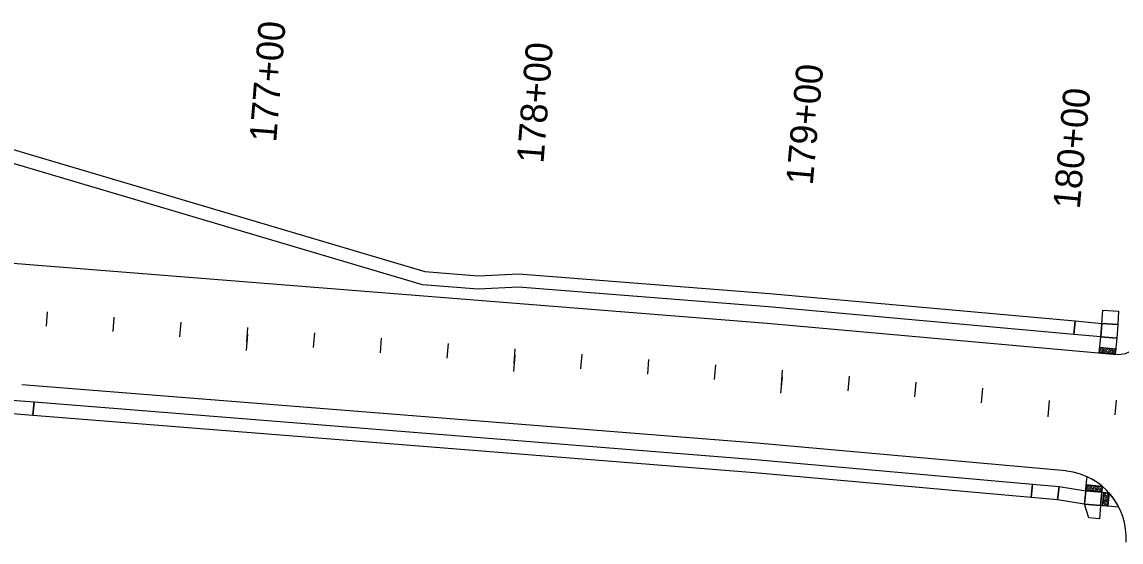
# Model space of a CAD drawing. Extents: x 20499216 to 20505321, y 7953487 to 7960535.
# Drawn here: x 20501326 to 20501735.9, y 7953850 to 7954043.9 of the extents above; entities that cross this region are included whole.
import ezdxf

# ---------------------------------------------------------------- set-up
doc = ezdxf.new("R2010")
doc.units = 0
for name, color, linetype in [('Drainage', 7, 'Continuous'), ('EXT_CU', 7, 'Continuous'), ('EXT_RR', 7, 'Continuous'), ('NamedBoundary', 7, 'Continuous'), ('Roadways', 7, 'Continuous'), ('Safety', 7, 'Continuous')]:
    doc.layers.add(name, color=color, linetype=linetype)

msp = doc.modelspace()

# ---------------------------------------------------------------- linework, layer by layer
at = {"layer": 'Drainage'}
for points in [[(20501729.07, 7953936.47), (20501734.99, 7953936.05), (20501734.63, 7953931.06), (20501728.74, 7953931.48)], [(20501718.78, 7953932.38), (20501728.75, 7953931.48), (20501728.29, 7953926.5), (20501718.33, 7953927.4)], [(20501728.29, 7953926.5), (20501734.26, 7953925.92), (20501733.69, 7953920), (20501727.71, 7953920.53)], [(20501330.05, 7953897.2), (20501315.1, 7953898.39), (20501315.5, 7953903.38), (20501330.45, 7953902.19)], [(20501712.8, 7953870.66), (20501712.18, 7953865.7), (20501702.4, 7953866.57), (20501702.84, 7953871.55)], [(20501722.08, 7953864.1), (20501712.18, 7953865.7), (20501712.8, 7953870.66), (20501722.7, 7953869.06), (20501722.25, 7953864.08)], [(20501722.91, 7953871.24), (20501728.89, 7953870.71), (20501728.69, 7953868.53), (20501722.7, 7953869.06)], [(20501730.94, 7953863.3), (20501728.23, 7953863.55), (20501728.68, 7953868.53), (20501731.39, 7953868.28)], [(20501727.8, 7953858.68), (20501723.86, 7953859.03), (20501722.25, 7953864.08), (20501728.23, 7953863.55), (20501727.8, 7953858.68)]]:
    msp.add_lwpolyline(points, close=True, dxfattribs=at)
for points in [[(20501728.89, 7953870.71), (20501722.91, 7953871.24), (20501723.21, 7953874.31)], [(20501735.06, 7953862.94), (20501730.94, 7953863.3), (20501731.39, 7953868.28)]]:
    msp.add_lwpolyline(points, dxfattribs=at)
for start, end in [(49.8891, 65.3451), (26.9932, 41.8993)]:
    msp.add_arc((20501712.78, 7953851.59), 25, start, end, dxfattribs=at)
at = {"layer": 'EXT_CU'}
for p, q in [((20501727.71, 7953920.58), (20501727.91, 7953922.57)), ((20501733.69, 7953920), (20501727.71, 7953920.58)), ((20501727.91, 7953922.57), (20501733.88, 7953921.99)), ((20501733.88, 7953921.99), (20501733.69, 7953920)), ((20501722.73, 7953869.25), (20501722.91, 7953871.24)), ((20501728.71, 7953868.72), (20501722.73, 7953869.25)), ((20501722.91, 7953871.24), (20501728.89, 7953870.71)), ((20501728.89, 7953870.71), (20501728.71, 7953868.72)), ((20501728.95, 7953863.48), (20501729.4, 7953868.46)), ((20501729.4, 7953868.46), (20501731.39, 7953868.28)), ((20501731.39, 7953868.28), (20501730.94, 7953863.3)), ((20501730.94, 7953863.3), (20501728.95, 7953863.48))]:
    msp.add_line(p, q, dxfattribs=at)
for points in [[(20500965.3, 7953991.78), (20501114.4, 7954012.75), (20501316.65, 7953998.09), (20501476.2, 7953950.79), (20501496.14, 7953949.21), (20501511.25, 7953950.02), (20501604.78, 7953942.58), (20501718.78, 7953932.38), (20501718.33, 7953927.4), (20501604.36, 7953937.6), (20501511.18, 7953945), (20501496.07, 7953944.2), (20501475.28, 7953945.85), (20501320.22, 7953991.82), (20501114.61, 7954006.72), (20500966.14, 7953985.84), (20500961.2, 7953986.29), (20500961.66, 7953991.27)], [(20501702.4, 7953866.57), (20501599.14, 7953875.82), (20501330.05, 7953897.2), (20501330.45, 7953902.19), (20501599.56, 7953880.8), (20501702.84, 7953871.55)]]:
    msp.add_lwpolyline(points, close=True, dxfattribs=at)
for centre, radius in [((20501729.54, 7953867.52), 0.0375), ((20501729.54, 7953867.52), 0.0187), ((20501729.57, 7953867.91), 0.0375), ((20501729.57, 7953867.91), 0.0187), ((20501729.61, 7953868.3), 0.0375), ((20501729.61, 7953868.3), 0.0187), ((20501729.93, 7953867.49), 0.0375), ((20501729.93, 7953867.49), 0.0187), ((20501729.96, 7953867.88), 0.0375), ((20501729.96, 7953867.88), 0.0187), ((20501730, 7953868.27), 0.0375), ((20501730, 7953868.27), 0.0187), ((20501730.32, 7953867.45), 0.0375), ((20501730.32, 7953867.45), 0.0187), ((20501730.35, 7953867.84), 0.0375), ((20501730.35, 7953867.84), 0.0187), ((20501730.39, 7953868.23), 0.0375), ((20501730.39, 7953868.23), 0.0187), ((20501730.71, 7953867.42), 0.0375), ((20501730.71, 7953867.42), 0.0187), ((20501730.74, 7953867.81), 0.0375), ((20501730.74, 7953867.81), 0.0187), ((20501730.78, 7953868.2), 0.0375), ((20501730.78, 7953868.2), 0.0187), ((20501731.1, 7953867.38), 0.0375), ((20501731.1, 7953867.38), 0.0187), ((20501731.13, 7953867.77), 0.0375), ((20501731.13, 7953867.77), 0.0187), ((20501731.17, 7953868.16), 0.0375), ((20501731.17, 7953868.16), 0.0187), ((20501729.19, 7953863.6), 0.0375), ((20501729.19, 7953863.6), 0.0187), ((20501729.22, 7953863.99), 0.0375), ((20501729.22, 7953863.99), 0.0187), ((20501729.26, 7953864.38), 0.0375), ((20501729.26, 7953864.38), 0.0187), ((20501729.29, 7953864.79), 0.0375), ((20501729.29, 7953864.79), 0.0187), ((20501729.33, 7953865.18), 0.0375), ((20501729.33, 7953865.18), 0.0187), ((20501729.36, 7953865.57), 0.0375), ((20501729.36, 7953865.57), 0.0187), ((20501729.4, 7953865.96), 0.0375), ((20501729.4, 7953865.96), 0.0187), ((20501729.43, 7953866.35), 0.0375), ((20501729.43, 7953866.35), 0.0187), ((20501729.47, 7953866.74), 0.0375), ((20501729.47, 7953866.74), 0.0187), ((20501729.5, 7953867.13), 0.0375), ((20501729.5, 7953867.13), 0.0187), ((20501729.58, 7953863.57), 0.0375), ((20501729.58, 7953863.57), 0.0187), ((20501729.61, 7953863.96), 0.0375), ((20501729.61, 7953863.96), 0.0187), ((20501729.65, 7953864.35), 0.0375), ((20501729.65, 7953864.35), 0.0187), ((20501729.68, 7953864.76), 0.0375), ((20501729.68, 7953864.76), 0.0187), ((20501729.72, 7953865.15), 0.0375), ((20501729.72, 7953865.15), 0.0187), ((20501729.75, 7953865.54), 0.0375), ((20501729.75, 7953865.54), 0.0187), ((20501729.79, 7953865.93), 0.0375), ((20501729.79, 7953865.93), 0.0187), ((20501729.82, 7953866.32), 0.0375), ((20501729.82, 7953866.32), 0.0187), ((20501729.86, 7953866.71), 0.0375), ((20501729.86, 7953866.71), 0.0187), ((20501729.89, 7953867.1), 0.0375), ((20501729.89, 7953867.1), 0.0187), ((20501729.97, 7953863.53), 0.0375), ((20501729.97, 7953863.53), 0.0187), ((20501730, 7953863.92), 0.0375), ((20501730, 7953863.92), 0.0187), ((20501730.04, 7953864.31), 0.0375), ((20501730.04, 7953864.31), 0.0187), ((20501730.07, 7953864.72), 0.0375), ((20501730.07, 7953864.72), 0.0187), ((20501730.11, 7953865.11), 0.0375), ((20501730.11, 7953865.11), 0.0187), ((20501730.14, 7953865.5), 0.0375), ((20501730.14, 7953865.5), 0.0187), ((20501730.18, 7953865.89), 0.0375), ((20501730.18, 7953865.89), 0.0187), ((20501730.21, 7953866.28), 0.0375), ((20501730.21, 7953866.28), 0.0187), ((20501730.25, 7953866.67), 0.0375), ((20501730.25, 7953866.67), 0.0187), ((20501730.28, 7953867.06), 0.0375), ((20501730.28, 7953867.06), 0.0187), ((20501730.36, 7953863.5), 0.0375), ((20501730.36, 7953863.5), 0.0187), ((20501730.39, 7953863.89), 0.0375), ((20501730.39, 7953863.89), 0.0187), ((20501730.43, 7953864.28), 0.0375), ((20501730.43, 7953864.28), 0.0187), ((20501730.46, 7953864.69), 0.0375), ((20501730.46, 7953864.69), 0.0187), ((20501730.5, 7953865.08), 0.0375), ((20501730.5, 7953865.08), 0.0187), ((20501730.53, 7953865.47), 0.0375), ((20501730.53, 7953865.47), 0.0187), ((20501730.57, 7953865.86), 0.0375), ((20501730.57, 7953865.86), 0.0187), ((20501730.6, 7953866.25), 0.0375), ((20501730.6, 7953866.25), 0.0187), ((20501730.64, 7953866.64), 0.0375), ((20501730.64, 7953866.64), 0.0187), ((20501730.67, 7953867.03), 0.0375), ((20501730.67, 7953867.03), 0.0187), ((20501730.75, 7953863.46), 0.0375), ((20501730.75, 7953863.46), 0.0187), ((20501730.78, 7953863.85), 0.0375), ((20501730.78, 7953863.85), 0.0187), ((20501730.82, 7953864.24), 0.0375), ((20501730.82, 7953864.24), 0.0187), ((20501730.85, 7953864.65), 0.0375), ((20501730.85, 7953864.65), 0.0187), ((20501730.89, 7953865.04), 0.0375), ((20501730.89, 7953865.04), 0.0187), ((20501730.92, 7953865.43), 0.0375), ((20501730.92, 7953865.43), 0.0187), ((20501730.96, 7953865.82), 0.0375), ((20501730.96, 7953865.82), 0.0187), ((20501730.99, 7953866.21), 0.0375), ((20501730.99, 7953866.21), 0.0187), ((20501731.03, 7953866.6), 0.0375), ((20501731.03, 7953866.6), 0.0187), ((20501731.06, 7953866.99), 0.0375), ((20501731.06, 7953866.99), 0.0187)]:
    msp.add_circle(centre, radius, dxfattribs=at)
for centre, major_axis in [((20501727.9, 7953920.77), (-0.0448, 0.0044)), ((20501727.9, 7953920.77), (-0.0224, 0.0022)), ((20501727.94, 7953921.16), (-0.0448, 0.0044)), ((20501727.94, 7953921.16), (-0.0224, 0.0022)), ((20501727.98, 7953921.55), (-0.0448, 0.0044)), ((20501727.98, 7953921.55), (-0.0224, 0.0022)), ((20501728.01, 7953921.94), (-0.0448, 0.0044)), ((20501728.01, 7953921.94), (-0.0224, 0.0022)), ((20501728.05, 7953922.33), (-0.0448, 0.0044)), ((20501728.05, 7953922.33), (-0.0224, 0.0022)), ((20501728.37, 7953920.73), (-0.0448, 0.0044)), ((20501728.37, 7953920.73), (-0.0224, 0.0022)), ((20501728.4, 7953921.12), (-0.0448, 0.0044)), ((20501728.4, 7953921.12), (-0.0224, 0.0022)), ((20501728.44, 7953921.51), (-0.0448, 0.0044)), ((20501728.44, 7953921.51), (-0.0224, 0.0022)), ((20501728.48, 7953921.9), (-0.0448, 0.0044)), ((20501728.48, 7953921.9), (-0.0224, 0.0022)), ((20501728.52, 7953922.29), (-0.0448, 0.0044)), ((20501728.52, 7953922.29), (-0.0224, 0.0022)), ((20501728.83, 7953920.68), (-0.0448, 0.0044)), ((20501728.83, 7953920.68), (-0.0224, 0.0022)), ((20501728.87, 7953921.07), (-0.0448, 0.0044)), ((20501728.87, 7953921.07), (-0.0224, 0.0022)), ((20501728.91, 7953921.46), (-0.0448, 0.0044)), ((20501728.91, 7953921.46), (-0.0224, 0.0022)), ((20501728.95, 7953921.85), (-0.0448, 0.0044)), ((20501728.95, 7953921.85), (-0.0224, 0.0022)), ((20501728.99, 7953922.24), (-0.0448, 0.0044)), ((20501728.99, 7953922.24), (-0.0224, 0.0022)), ((20501729.33, 7953920.63), (-0.0448, 0.0044)), ((20501729.33, 7953920.63), (-0.0224, 0.0022)), ((20501729.37, 7953921.02), (-0.0448, 0.0044)), ((20501729.37, 7953921.02), (-0.0224, 0.0022)), ((20501729.4, 7953921.41), (-0.0448, 0.0044)), ((20501729.4, 7953921.41), (-0.0224, 0.0022)), ((20501729.44, 7953921.8), (-0.0448, 0.0044)), ((20501729.44, 7953921.8), (-0.0224, 0.0022)), ((20501729.48, 7953922.19), (-0.0448, 0.0044)), ((20501729.48, 7953922.19), (-0.0224, 0.0022)), ((20501729.8, 7953920.59), (-0.0448, 0.0044)), ((20501729.8, 7953920.59), (-0.0224, 0.0022)), ((20501729.83, 7953920.98), (-0.0448, 0.0044)), ((20501729.83, 7953920.98), (-0.0224, 0.0022)), ((20501729.87, 7953921.37), (-0.0448, 0.0044)), ((20501729.87, 7953921.37), (-0.0224, 0.0022)), ((20501729.91, 7953921.76), (-0.0448, 0.0044)), ((20501729.91, 7953921.76), (-0.0224, 0.0022)), ((20501729.95, 7953922.15), (-0.0448, 0.0044)), ((20501729.95, 7953922.15), (-0.0224, 0.0022)), ((20501730.26, 7953920.54), (-0.0448, 0.0044)), ((20501730.3, 7953920.93), (-0.0448, 0.0044)), ((20501730.3, 7953920.93), (-0.0224, 0.0022)), ((20501730.34, 7953921.32), (-0.0448, 0.0044)), ((20501730.34, 7953921.32), (-0.0224, 0.0022)), ((20501730.38, 7953921.71), (-0.0448, 0.0044)), ((20501730.38, 7953921.71), (-0.0224, 0.0022)), ((20501730.41, 7953922.1), (-0.0448, 0.0044)), ((20501730.41, 7953922.1), (-0.0224, 0.0022)), ((20501730.77, 7953920.89), (-0.0448, 0.0044)), ((20501730.77, 7953920.89), (-0.0224, 0.0022)), ((20501730.81, 7953921.28), (-0.0448, 0.0044)), ((20501730.81, 7953921.28), (-0.0224, 0.0022)), ((20501730.84, 7953921.67), (-0.0448, 0.0044)), ((20501730.84, 7953921.67), (-0.0224, 0.0022)), ((20501730.88, 7953922.06), (-0.0448, 0.0044)), ((20501730.88, 7953922.06), (-0.0224, 0.0022)), ((20501731.24, 7953920.84), (-0.0448, 0.0044)), ((20501731.24, 7953920.84), (-0.0224, 0.0022)), ((20501731.27, 7953921.23), (-0.0448, 0.0044)), ((20501731.27, 7953921.23), (-0.0224, 0.0022)), ((20501731.31, 7953921.62), (-0.0448, 0.0044)), ((20501731.31, 7953921.62), (-0.0224, 0.0022)), ((20501731.35, 7953922.01), (-0.0448, 0.0044)), ((20501731.35, 7953922.01), (-0.0224, 0.0022)), ((20501731.7, 7953920.8), (-0.0448, 0.0044)), ((20501731.7, 7953920.8), (-0.0224, 0.0022)), ((20501731.74, 7953921.18), (-0.0448, 0.0044)), ((20501731.74, 7953921.18), (-0.0224, 0.0022)), ((20501731.78, 7953921.57), (-0.0448, 0.0044)), ((20501731.78, 7953921.57), (-0.0224, 0.0022)), ((20501731.82, 7953921.96), (-0.0448, 0.0044)), ((20501731.82, 7953921.96), (-0.0224, 0.0022)), ((20501732.17, 7953920.75), (-0.0448, 0.0044)), ((20501732.17, 7953920.75), (-0.0224, 0.0022)), ((20501732.21, 7953921.14), (-0.0448, 0.0044)), ((20501732.21, 7953921.14), (-0.0224, 0.0022)), ((20501732.25, 7953921.53), (-0.0448, 0.0044)), ((20501732.25, 7953921.53), (-0.0224, 0.0022)), ((20501732.29, 7953921.92), (-0.0448, 0.0044)), ((20501732.29, 7953921.92), (-0.0224, 0.0022)), ((20501732.64, 7953920.7), (-0.0448, 0.0044)), ((20501732.64, 7953920.7), (-0.0224, 0.0022)), ((20501732.68, 7953921.09), (-0.0448, 0.0044)), ((20501732.68, 7953921.09), (-0.0224, 0.0022)), ((20501732.72, 7953921.48), (-0.0448, 0.0044)), ((20501732.72, 7953921.48), (-0.0224, 0.0022)), ((20501732.75, 7953921.87), (-0.0448, 0.0044)), ((20501732.75, 7953921.87), (-0.0224, 0.0022)), ((20501733.11, 7953920.66), (-0.0448, 0.0044)), ((20501733.11, 7953920.66), (-0.0224, 0.0022)), ((20501733.15, 7953921.05), (-0.0448, 0.0044)), ((20501733.15, 7953921.05), (-0.0224, 0.0022)), ((20501733.18, 7953921.44), (-0.0448, 0.0044)), ((20501733.18, 7953921.44), (-0.0224, 0.0022)), ((20501733.22, 7953921.83), (-0.0448, 0.0044)), ((20501733.22, 7953921.83), (-0.0224, 0.0022)), ((20501733.57, 7953920.61), (-0.0448, 0.0044)), ((20501733.57, 7953920.61), (-0.0224, 0.0022)), ((20501733.61, 7953921), (-0.0448, 0.0044)), ((20501733.61, 7953921), (-0.0224, 0.0022)), ((20501733.65, 7953921.39), (-0.0448, 0.0044)), ((20501733.65, 7953921.39), (-0.0224, 0.0022)), ((20501733.69, 7953921.78), (-0.0448, 0.0044)), ((20501733.69, 7953921.78), (-0.0224, 0.0022)), ((20501730.26, 7953920.54), (-0.0224, 0.0022)), ((20501730.73, 7953920.5), (-0.0448, 0.0044)), ((20501730.73, 7953920.5), (-0.0224, 0.0022)), ((20501731.2, 7953920.45), (-0.0448, 0.0044)), ((20501731.2, 7953920.45), (-0.0224, 0.0022)), ((20501731.67, 7953920.41), (-0.0448, 0.0044)), ((20501731.67, 7953920.41), (-0.0224, 0.0022)), ((20501732.13, 7953920.36), (-0.0448, 0.0044)), ((20501732.13, 7953920.36), (-0.0224, 0.0022)), ((20501732.6, 7953920.31), (-0.0448, 0.0044)), ((20501732.6, 7953920.31), (-0.0224, 0.0022)), ((20501733.07, 7953920.27), (-0.0448, 0.0044)), ((20501733.07, 7953920.27), (-0.0224, 0.0022)), ((20501733.54, 7953920.22), (-0.0448, 0.0044)), ((20501733.54, 7953920.22), (-0.0224, 0.0022)), ((20501722.92, 7953869.45), (-0.0448, 0.004)), ((20501722.92, 7953869.45), (-0.0224, 0.002)), ((20501722.95, 7953869.84), (-0.0448, 0.004)), ((20501722.95, 7953869.84), (-0.0224, 0.002)), ((20501722.99, 7953870.23), (-0.0448, 0.004)), ((20501722.99, 7953870.23), (-0.0224, 0.002)), ((20501723.02, 7953870.62), (-0.0448, 0.004)), ((20501723.02, 7953870.62), (-0.0224, 0.002)), ((20501723.06, 7953871.01), (-0.0448, 0.004)), ((20501723.06, 7953871.01), (-0.0224, 0.002)), ((20501723.39, 7953869.4), (-0.0448, 0.004)), ((20501723.39, 7953869.4), (-0.0224, 0.002)), ((20501723.42, 7953869.79), (-0.0448, 0.004)), ((20501723.42, 7953869.79), (-0.0224, 0.002)), ((20501723.46, 7953870.19), (-0.0448, 0.004)), ((20501723.46, 7953870.19), (-0.0224, 0.002)), ((20501723.49, 7953870.58), (-0.0448, 0.004)), ((20501723.49, 7953870.58), (-0.0224, 0.002)), ((20501723.53, 7953870.97), (-0.0448, 0.004)), ((20501723.53, 7953870.97), (-0.0224, 0.002)), ((20501723.86, 7953869.36), (-0.0448, 0.004)), ((20501723.86, 7953869.36), (-0.0224, 0.002)), ((20501723.89, 7953869.75), (-0.0448, 0.004)), ((20501723.89, 7953869.75), (-0.0224, 0.002)), ((20501723.92, 7953870.14), (-0.0448, 0.004)), ((20501723.92, 7953870.14), (-0.0224, 0.002)), ((20501723.96, 7953870.53), (-0.0448, 0.004)), ((20501723.96, 7953870.53), (-0.0224, 0.002)), ((20501723.99, 7953870.92), (-0.0448, 0.004)), ((20501723.99, 7953870.92), (-0.0224, 0.002)), ((20501724.35, 7953869.32), (-0.0448, 0.004)), ((20501724.35, 7953869.32), (-0.0224, 0.002)), ((20501724.38, 7953869.71), (-0.0448, 0.004)), ((20501724.38, 7953869.71), (-0.0224, 0.002)), ((20501724.42, 7953870.1), (-0.0448, 0.004)), ((20501724.42, 7953870.1), (-0.0224, 0.002)), ((20501724.45, 7953870.49), (-0.0448, 0.004)), ((20501724.45, 7953870.49), (-0.0224, 0.002)), ((20501724.49, 7953870.88), (-0.0448, 0.004)), ((20501724.49, 7953870.88), (-0.0224, 0.002)), ((20501724.82, 7953869.28), (-0.0448, 0.004)), ((20501724.82, 7953869.28), (-0.0224, 0.002)), ((20501724.85, 7953869.67), (-0.0448, 0.004)), ((20501724.85, 7953869.67), (-0.0224, 0.002)), ((20501724.89, 7953870.06), (-0.0448, 0.004)), ((20501724.89, 7953870.06), (-0.0224, 0.002)), ((20501724.92, 7953870.45), (-0.0448, 0.004)), ((20501724.92, 7953870.45), (-0.0224, 0.002)), ((20501724.96, 7953870.84), (-0.0448, 0.004)), ((20501724.96, 7953870.84), (-0.0224, 0.002)), ((20501725.28, 7953869.23), (-0.0448, 0.004)), ((20501725.28, 7953869.23), (-0.0224, 0.002)), ((20501725.32, 7953869.63), (-0.0448, 0.004)), ((20501725.32, 7953869.63), (-0.0224, 0.002)), ((20501725.35, 7953870.02), (-0.0448, 0.004)), ((20501725.35, 7953870.02), (-0.0224, 0.002)), ((20501725.39, 7953870.41), (-0.0448, 0.004)), ((20501725.39, 7953870.41), (-0.0224, 0.002)), ((20501725.42, 7953870.8), (-0.0448, 0.004)), ((20501725.42, 7953870.8), (-0.0224, 0.002)), ((20501725.75, 7953869.19), (-0.0448, 0.004)), ((20501725.75, 7953869.19), (-0.0224, 0.002)), ((20501725.79, 7953869.58), (-0.0448, 0.004)), ((20501725.79, 7953869.58), (-0.0224, 0.002)), ((20501725.82, 7953869.97), (-0.0448, 0.004)), ((20501725.82, 7953869.97), (-0.0224, 0.002)), ((20501725.86, 7953870.36), (-0.0448, 0.004)), ((20501725.86, 7953870.36), (-0.0224, 0.002)), ((20501725.89, 7953870.75), (-0.0448, 0.004)), ((20501725.89, 7953870.75), (-0.0224, 0.002)), ((20501726.22, 7953869.15), (-0.0448, 0.004)), ((20501726.22, 7953869.15), (-0.0224, 0.002)), ((20501726.26, 7953869.54), (-0.0448, 0.004)), ((20501726.26, 7953869.54), (-0.0224, 0.002)), ((20501726.29, 7953869.93), (-0.0448, 0.004)), ((20501726.29, 7953869.93), (-0.0224, 0.002)), ((20501726.33, 7953870.32), (-0.0448, 0.004)), ((20501726.33, 7953870.32), (-0.0224, 0.002)), ((20501726.36, 7953870.71), (-0.0448, 0.004)), ((20501726.36, 7953870.71), (-0.0224, 0.002)), ((20501726.69, 7953869.11), (-0.0448, 0.004)), ((20501726.69, 7953869.11), (-0.0224, 0.002)), ((20501726.72, 7953869.5), (-0.0448, 0.004)), ((20501726.72, 7953869.5), (-0.0224, 0.002)), ((20501726.76, 7953869.89), (-0.0448, 0.004)), ((20501726.76, 7953869.89), (-0.0224, 0.002)), ((20501726.79, 7953870.28), (-0.0448, 0.004)), ((20501726.79, 7953870.28), (-0.0224, 0.002)), ((20501726.83, 7953870.67), (-0.0448, 0.004)), ((20501726.83, 7953870.67), (-0.0224, 0.002)), ((20501727.16, 7953869.07), (-0.0448, 0.004)), ((20501727.16, 7953869.07), (-0.0224, 0.002)), ((20501727.19, 7953869.46), (-0.0448, 0.004)), ((20501727.19, 7953869.46), (-0.0224, 0.002)), ((20501727.23, 7953869.85), (-0.0448, 0.004)), ((20501727.23, 7953869.85), (-0.0224, 0.002)), ((20501727.26, 7953870.24), (-0.0448, 0.004)), ((20501727.26, 7953870.24), (-0.0224, 0.002)), ((20501727.3, 7953870.63), (-0.0448, 0.004)), ((20501727.3, 7953870.63), (-0.0224, 0.002)), ((20501727.62, 7953869.03), (-0.0448, 0.004)), ((20501727.62, 7953869.03), (-0.0224, 0.002)), ((20501727.66, 7953869.42), (-0.0448, 0.004)), ((20501727.66, 7953869.42), (-0.0224, 0.002)), ((20501727.69, 7953869.81), (-0.0448, 0.004)), ((20501727.69, 7953869.81), (-0.0224, 0.002)), ((20501727.73, 7953870.2), (-0.0448, 0.004)), ((20501727.73, 7953870.2), (-0.0224, 0.002)), ((20501727.76, 7953870.59), (-0.0448, 0.004)), ((20501727.76, 7953870.59), (-0.0224, 0.002)), ((20501728.09, 7953868.98), (-0.0448, 0.004)), ((20501728.09, 7953868.98), (-0.0224, 0.002)), ((20501728.13, 7953869.37), (-0.0448, 0.004)), ((20501728.13, 7953869.37), (-0.0224, 0.002)), ((20501728.16, 7953869.76), (-0.0448, 0.004)), ((20501728.16, 7953869.76), (-0.0224, 0.002)), ((20501728.2, 7953870.15), (-0.0448, 0.004)), ((20501728.2, 7953870.15), (-0.0224, 0.002)), ((20501728.23, 7953870.54), (-0.0448, 0.004)), ((20501728.23, 7953870.54), (-0.0224, 0.002)), ((20501728.56, 7953868.94), (-0.0448, 0.004)), ((20501728.56, 7953868.94), (-0.0224, 0.002)), ((20501728.6, 7953869.33), (-0.0448, 0.004)), ((20501728.6, 7953869.33), (-0.0224, 0.002)), ((20501728.63, 7953869.72), (-0.0448, 0.004)), ((20501728.63, 7953869.72), (-0.0224, 0.002)), ((20501728.67, 7953870.11), (-0.0448, 0.004)), ((20501728.67, 7953870.11), (-0.0224, 0.002)), ((20501728.7, 7953870.5), (-0.0448, 0.004)), ((20501728.7, 7953870.5), (-0.0224, 0.002))]:
    msp.add_ellipse(centre, major_axis=major_axis, ratio=0.833333, dxfattribs=at)
at = {"layer": 'EXT_RR'}
for p, q in [((20501335.05, 7953930.41), (20501335.48, 7953935.85)), ((20501359.97, 7953928.43), (20501360.4, 7953933.87)), ((20501384.89, 7953926.45), (20501385.33, 7953931.89)), ((20501410.06, 7953927.52), (20501409.57, 7953921.42)), ((20501434.74, 7953922.49), (20501435.17, 7953927.93)), ((20501459.66, 7953920.51), (20501460.09, 7953925.95)), ((20501484.58, 7953918.53), (20501485.01, 7953923.97)), ((20501509.74, 7953919.6), (20501509.26, 7953913.5)), ((20501534.42, 7953914.57), (20501534.85, 7953920.01)), ((20501559.34, 7953912.59), (20501559.78, 7953918.03)), ((20501584.26, 7953910.61), (20501584.7, 7953916.05)), ((20501609.45, 7953911.6), (20501608.91, 7953905.51)), ((20501634.08, 7953906.33), (20501634.57, 7953911.76)), ((20501658.98, 7953904.1), (20501659.47, 7953909.53)), ((20501683.88, 7953901.87), (20501684.37, 7953907.3)), ((20501709.05, 7953902.68), (20501708.51, 7953896.59)), ((20501733.68, 7953897.41), (20501734.17, 7953902.84))]:
    msp.add_line(p, q, dxfattribs=at)
at = {"layer": 'NamedBoundary'}
for points in [[(20500911.34, 7953941.51), (20500848.24, 7953946.53), (20500808.56, 7953950.16), (20500808.63, 7953950.91), (20500808.63, 7953950.91), (20500809.17, 7953955.67), (20500809.06, 7953955.68), (20500812.15, 7953989.44), (20500804.8, 7953990.07), (20500805.25, 7953995.63), (20500812.66, 7953994.97), (20500852.08, 7953991.36), (20501603.86, 7953931.62), (20501734.26, 7953919.95)], [(20501715.63, 7953876.43), (20501715.33, 7953876.46), (20501600.07, 7953886.78), (20501325.96, 7953908.56), (20501325.96, 7953908.56)]]:
    msp.add_lwpolyline(points, dxfattribs=at)
for centre, radius, start, end in [((20501735.01, 7953928.41), 8.5, 264.8834, 354.618), ((20501712.76, 7953851.57), 25.03, 356.3606, 83.4061)]:
    msp.add_arc(centre, radius, start, end, dxfattribs=at)
at = {"layer": 'Roadways'}
for points in [[(20501728.74, 7953931.48), (20501734.63, 7953931.06), (20501734.63, 7953930.96), (20501734.26, 7953925.92), (20501728.29, 7953926.5)], [(20501722.25, 7953864.08), (20501722.7, 7953869.06), (20501728.68, 7953868.53), (20501728.23, 7953863.55)]]:
    msp.add_lwpolyline(points, close=True, dxfattribs=at)
at = {"layer": 'Safety'}
for p, q in [((20501409.81, 7953924.47), (20501410.25, 7953929.91)), ((20501509.5, 7953916.55), (20501509.93, 7953921.99)), ((20501609.18, 7953908.55), (20501609.67, 7953913.99)), ((20501709.05, 7953902.68), (20501708.51, 7953896.59))]:
    msp.add_line(p, q, dxfattribs=at)

# ---------------------------------------------------------------- texts
at = {"layer": 'EXT_RR'}
for s, rotation, p in [('177+00', 85.4564, (20501420.75, 7953998.84)), ('178+00', 85.4564, (20501520.44, 7953990.92)), ('179+00', 84.8834, (20501620.86, 7953982.81)), ('180+00', 84.8834, (20501720.46, 7953973.89))]:
    msp.add_text(s, height=10.02, rotation=rotation, dxfattribs=at).set_placement(p)
at = {"layer": 'Safety'}
msp.add_text('180+00', height=10.02, rotation=84.8834, dxfattribs=at).set_placement((20501720.46, 7953973.89))

doc.saveas('drawing.dxf')
